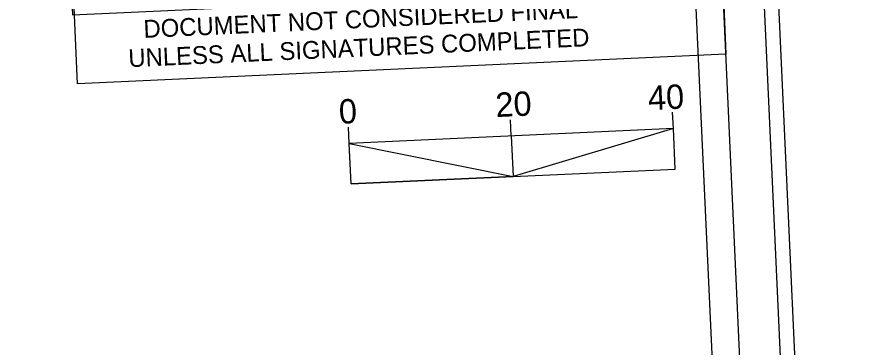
# Model space of a CAD drawing. Extents: x 1191070 to 1191932, y 892813 to 893283.
# Drawn here: x 1191699.2 to 1191803.2, y 893167.7 to 893208.4 of the extents above; entities that cross this region are included whole.
import ezdxf

# ---------------------------------------------------------------- set-up
doc = ezdxf.new("R2010")
doc.units = 0
for name, color, linetype in [('Sheet Border Standard 30in CELL', 7, 'Continuous'), ('Sheet Clip Boundary CELL', 7, 'Continuous'), ('Sheet Data Field CELL', 7, 'Continuous'), ('Sheet Plot Border Inside CELL', 7, 'Continuous'), ('Sheet Plot Border Outside CELL', 7, 'Continuous'), ('Sheet Sticker Exception Certification CELL', 7, 'Continuous'), ('Sheet Title CELL', 7, 'Continuous')]:
    doc.layers.add(name, color=color, linetype=linetype)

# ---------------------------------------------------------------- blocks, each defined once
blk = doc.blocks.new('STICKER EXCEPTION CERTIFICATION')
at = {"layer": 'Sheet Sticker Exception Certification CELL'}
for p, q in [((0, -0.47), (0, 0)), ((0, 0), (4.0008, 0)), ((4.0008, -0.0003), (4.0008, -0.4703)), ((4.0008, -0.47), (0, -0.47))]:
    blk.add_line(p, q, dxfattribs=at)
for s, p in [('DOCUMENT NOT CONSIDERED FINAL', (0.4214, -0.2069)), ('UNLESS ALL SIGNATURES COMPLETED', (0.32, -0.3829))]:
    blk.add_text(s, height=0.11, dxfattribs=at).set_placement(p)

msp = doc.modelspace()

# ---------------------------------------------------------------- linework, layer by layer
at = {"layer": 'Sheet Border Standard 30in CELL'}
msp.add_lwpolyline([(1191783.48, 893273.17), (1191184.11, 893245.75), (1191203.31, 892826.19), (1191802.68, 892853.61)], close=True, dxfattribs=at)
at = {"layer": 'Sheet Clip Boundary CELL'}
msp.add_lwpolyline([(1191201.31, 892936.07), (1191187.08, 893244.15), (1191703.39, 893267.99), (1191706.1, 893208.66), (1191782.81, 893212.17), (1191794.3, 892963.46), (1191451.08, 892947.61)], close=True, dxfattribs=at)
at = {"layer": 'Sheet Data Field CELL'}
for p, q in [((1191780.17, 893194.65), (1191780.08, 893196.65)), ((1191760.19, 893193.74), (1191760.1, 893195.73))]:
    msp.add_line(p, q, dxfattribs=at)
at = {"layer": 'Sheet Plot Border Inside CELL'}
msp.add_lwpolyline([(1191788.43, 893274.42), (1191122.53, 893243.95), (1191141.82, 892822.35), (1191807.72, 892852.82)], close=True, dxfattribs=at)
at = {"layer": 'Sheet Plot Border Outside CELL'}
msp.add_lwpolyline([(1191789.82, 893283.47), (1191116.92, 893252.68), (1191137.03, 892813.14), (1191809.93, 892843.93)], close=True, dxfattribs=at)
at = {"layer": 'Sheet Title CELL'}
for p, q in [((1191739.16, 893197.09), (1191739.16, 893197.09)), ((1191780.17, 893194.65), (1191780.08, 893196.64)), ((1191760.19, 893193.73), (1191760.1, 893195.72)), ((1191740.21, 893192.81), (1191740.12, 893194.81)), ((1191780.17, 893194.65), (1191740.21, 893192.82)), ((1191780.4, 893189.65), (1191780.17, 893194.65)), ((1191760.19, 893193.73), (1191760.42, 893188.74)), ((1191740.44, 893187.82), (1191780.4, 893189.65))]:
    msp.add_line(p, q, dxfattribs=at)
for points in [[(1191780.17, 893194.65), (1191760.42, 893188.74), (1191780.4, 893189.65)], [(1191740.21, 893192.81), (1191760.42, 893188.74), (1191740.44, 893187.82)]]:
    msp.add_lwpolyline(points, close=True, dxfattribs=at)

# ---------------------------------------------------------------- block references
at = {"layer": 'Sheet Sticker Exception Certification CELL', "xscale": 20, "yscale": 19.999999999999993, "rotation": 2.6194666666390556}
msp.add_blockref('STICKER EXCEPTION CERTIFICATION', (1191706.29, 893209.55), dxfattribs=at)

# ---------------------------------------------------------------- texts
at = {"layer": 'Sheet Data Field CELL'}
for s, p in [('40 ', (1191777.1, 893196.91)), ('20', (1191758.3, 893196.05))]:
    msp.add_text(s, height=3, rotation=2.6195, dxfattribs=at).set_placement(p)
at = {"layer": 'Sheet Title CELL'}
msp.add_text('0', height=3, rotation=2.6195, dxfattribs=at).set_placement((1191739, 893195.22))

doc.saveas('drawing.dxf')
